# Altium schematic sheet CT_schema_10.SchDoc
size 278 x 170 mm
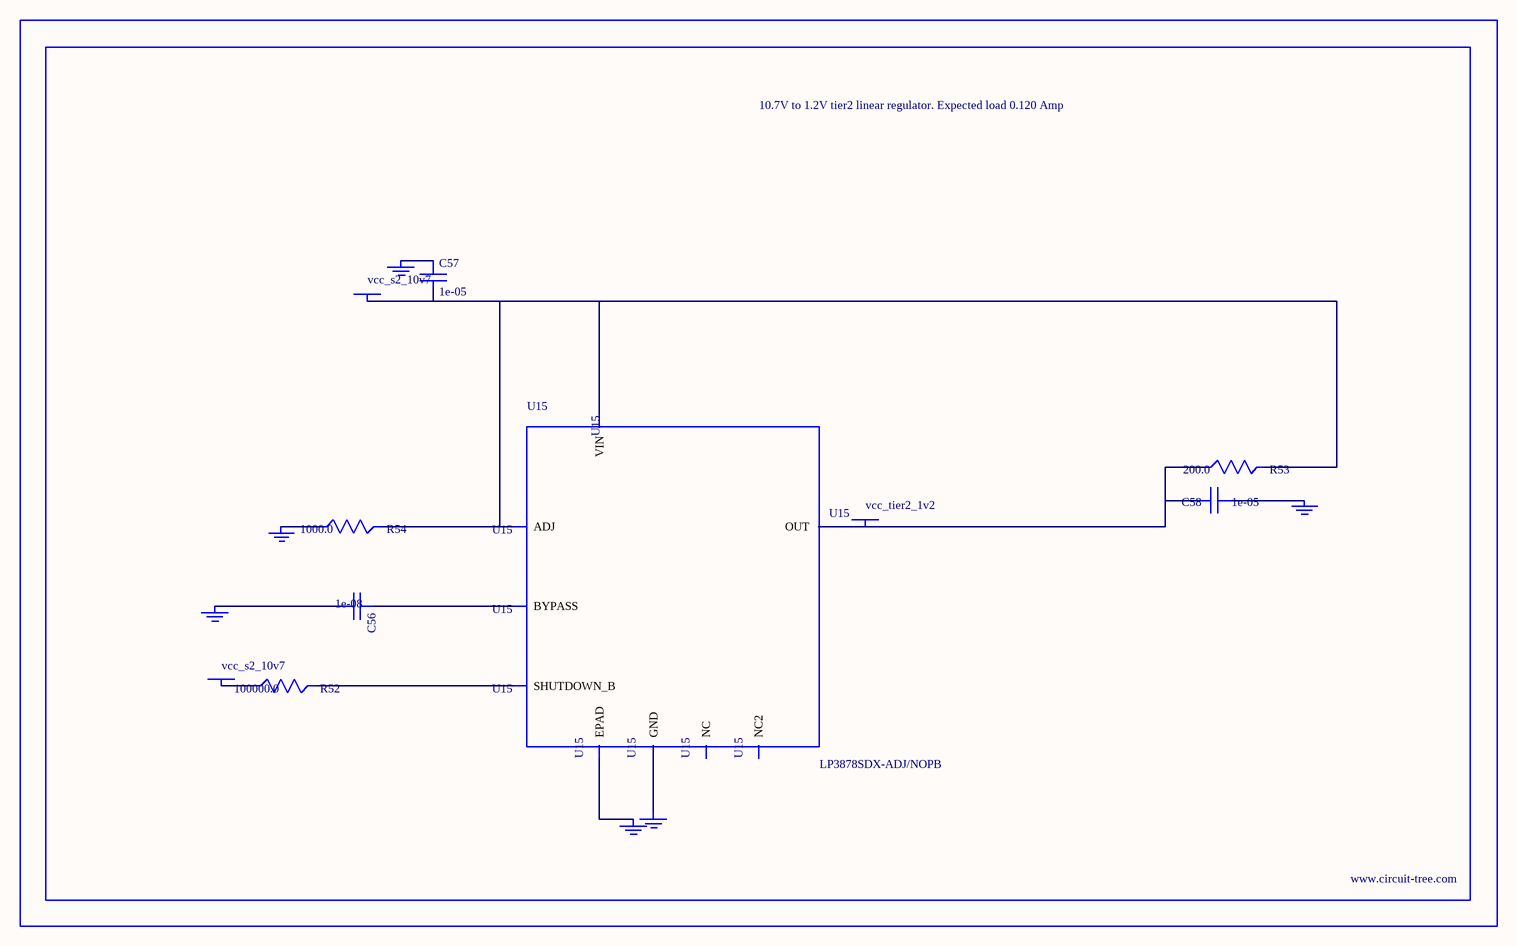
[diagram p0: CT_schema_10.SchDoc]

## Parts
BORDER9  (no value)
C56  1e-08  [C0402]
C57  1e-05  [C1206]
C58  1e-05  [C0805]
GND_INSTANCE_9_0  (no value)
GND_INSTANCE_9_1  (no value)
GND_INSTANCE_9_2  (no value)
GND_INSTANCE_9_3  (no value)
GND_INSTANCE_9_4  (no value)
GND_INSTANCE_9_5  (no value)
POWER_INSTANCE_9_0  vcc_s2_10v7
POWER_INSTANCE_9_1  vcc_s2_10v7
POWER_INSTANCE_9_2  vcc_tier2_1v2
R52  100000.0  [R0603]
R53  200.0  [R0603]
R54  1000.0  [R0603]
U15  LP3878SDX-ADJ/NOPB  [WSON-8]

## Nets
NetC56_1: C56.1 U15.1(BYPASS)
NetC56_2: C56.2 GND_INSTANCE_9_0.0(GND)
NetC57_1: C57.1 GND_INSTANCE_9_1.0(GND)
NetC57_2: C57.2 POWER_INSTANCE_9_0.0(PWR) R53.2 R54.2 U15.4(VIN) U15.6(ADJ)
NetC58_1: C58.1 GND_INSTANCE_9_2.0(GND)
NetC58_2: C58.2 POWER_INSTANCE_9_2.0(PWR) R53.1 U15.5(OUT)
NetGND_INSTANCE_9_3_0: GND_INSTANCE_9_3.0(GND) R54.1
NetGND_INSTANCE_9_4_0: GND_INSTANCE_9_4.0(GND) U15.PAD(EPAD)
NetGND_INSTANCE_9_5_0: GND_INSTANCE_9_5.0(GND) U15.3(GND)
NetPOWER_INSTANCE_9_1_0: POWER_INSTANCE_9_1.0(PWR) R52.1
NetR52_2: R52.2 U15.8(SHUTDOWN_B)

Not connected (* = marked no-connect by the designer): U15 2(NC) 7(NC2)

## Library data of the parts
BORDER9 = BORDER_PAGE9
C56 = C0402C103K3RAC
C57 = C1206C106K3RACTU
C58 = GRM219R60J106ME19D
GND_INSTANCE_9_0-GND_INSTANCE_9_5 = GND
POWER_INSTANCE_9_0-POWER_INSTANCE_9_2 = PWR
R52 = RC0603JR-07100KL
R53 = RC0603JR-07200RL
R54 = RC0603JR-071KL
